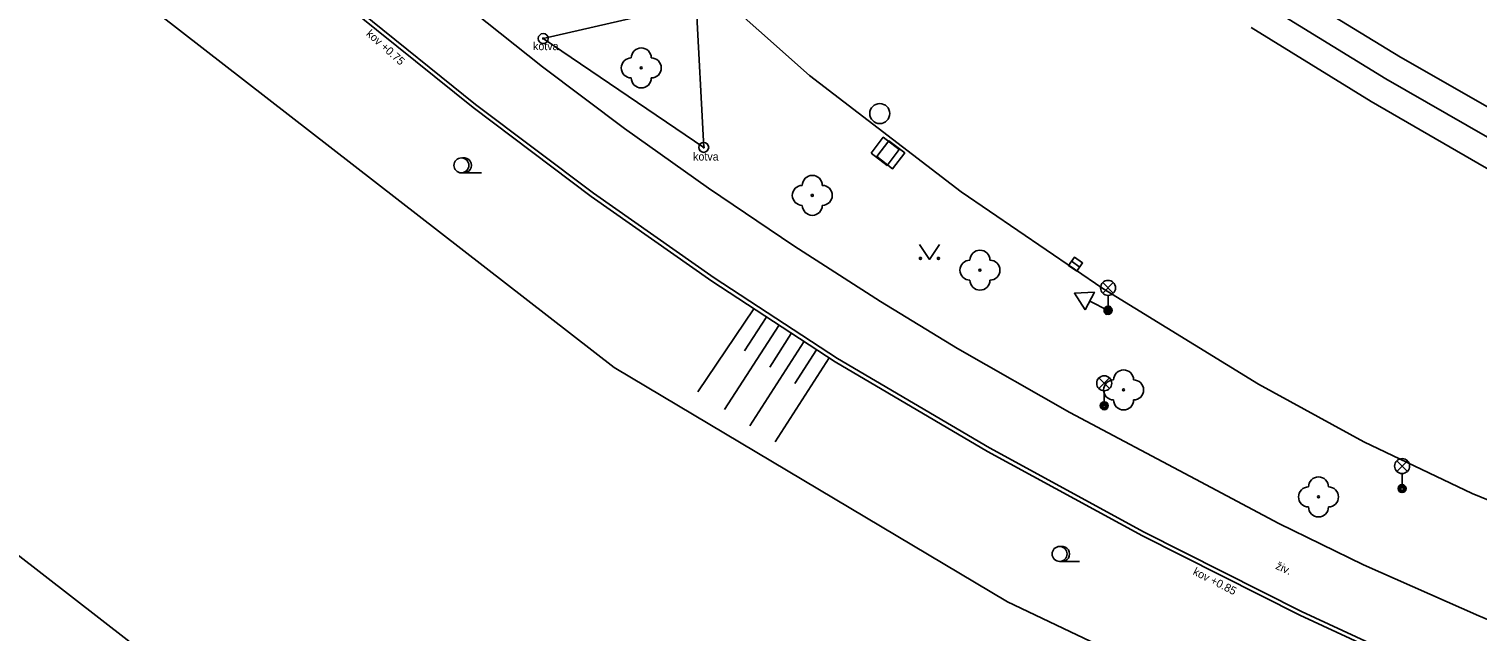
# Model space of a CAD drawing. Extents: x -598932 to -598196, y -1162207 to -1161504.
# Drawn here: x -598659.5 to -598587.2, y -1161999.2 to -1161969.1 of the extents above; entities that cross this region are included whole.
import ezdxf

# ---------------------------------------------------------------- set-up
doc = ezdxf.new("R2010")
doc.units = 0
for name, color, linetype in [('Level 22', 7, 'Continuous'), ('Level 25', 7, 'Continuous'), ('Level 26', 7, 'Continuous'), ('Level 27', 7, 'Continuous'), ('Level 33', 7, 'Continuous'), ('Level 34', 7, 'Continuous'), ('Level 36', 7, 'Continuous'), ('TM - CD - osa koleji', 7, 'Continuous'), ('TM - chodniky - VP', 7, 'Continuous'), ('TM - hladina vodniho toku_ bazenu_ nadrze', 7, 'Continuous'), ('TM - komunikace - VP', 7, 'Continuous'), ('TM - pomocna konstrukcna linie', 7, 'Continuous'), ('TM - popis povrchu', 7, 'Continuous'), ('TM - poznamka', 7, 'Continuous'), ('TM - rozhrani ploch obecne - VN', 7, 'Continuous'), ('TM - rozhrani ploch obecne - VP', 7, 'Continuous'), ('TM - srafovani', 7, 'Continuous'), ('TM - zabradli - VP', 7, 'Continuous')]:
    doc.layers.add(name, color=color, linetype=linetype)

msp = doc.modelspace()

# ---------------------------------------------------------------- linework, layer by layer
at = {"layer": 'Level 22'}
for centre in [(-598628.94, -1161971.06), (-598620.39, -1161977.43), (-598612.01, -1161981.17), (-598604.83, -1161987.16), (-598595.09, -1161992.51)]:
    msp.add_circle(centre, 0.05, dxfattribs=at)
for centre, start, end in [((-598628.94, -1161970.56), 0, 180), ((-598629.44, -1161971.06), 90, 270), ((-598628.44, -1161971.06), 270, 90), ((-598628.94, -1161971.56), 180, 0), ((-598620.89, -1161977.43), 90, 270), ((-598620.39, -1161976.93), 0, 180), ((-598619.89, -1161977.43), 270, 90), ((-598620.39, -1161977.93), 180, 0), ((-598612.01, -1161980.67), 0, 180), ((-598612.51, -1161981.17), 90, 270), ((-598611.51, -1161981.17), 270, 90), ((-598612.01, -1161981.67), 180, 0), ((-598604.83, -1161986.66), 0, 180), ((-598605.33, -1161987.16), 90, 270), ((-598604.33, -1161987.16), 270, 90), ((-598604.83, -1161987.66), 180, 0), ((-598595.59, -1161992.51), 90, 270), ((-598595.09, -1161992.01), 0, 180), ((-598594.59, -1161992.51), 270, 90), ((-598595.09, -1161993.01), 180, 0)]:
    msp.add_arc(centre, 0.5, start, end, dxfattribs=at)
at = {"layer": 'Level 25'}
for centre, radius in [((-598633.84, -1161969.59), 0.25), ((-598633.84, -1161969.59), 0.0303), ((-598625.82, -1161975.03), 0.25), ((-598625.82, -1161975.03), 0.0303)]:
    msp.add_circle(centre, radius, dxfattribs=at)
at = {"layer": 'Level 26'}
for points in [[(-598617.451, -1161975.323), (-598616.657, -1161975.931), (-598616.049, -1161975.137), (-598616.843, -1161974.529)], [(-598617.171, -1161975.493), (-598616.377, -1161976.101), (-598615.769, -1161975.307), (-598616.563, -1161974.699)]]:
    msp.add_lwpolyline(points, close=True, dxfattribs=at)
at = {"layer": 'Level 27'}
msp.add_line((-598607.435, -1161980.726), (-598607.025, -1161981.014), dxfattribs=at)
msp.add_lwpolyline([(-598607.578, -1161980.931), (-598607.169, -1161981.218), (-598606.882, -1161980.809), (-598607.291, -1161980.522)], close=True, dxfattribs=at)
msp.add_circle((-598617.02, -1161973.34), 0.5, dxfattribs=at)
at = {"layer": 'Level 33'}
for p, q in [((-598605.875, -1161982.32), (-598605.345, -1161981.79)), ((-598605.875, -1161981.79), (-598605.345, -1161982.32)), ((-598605.61, -1161982.43), (-598605.61, -1161983.18)), ((-598606.065, -1161987.09), (-598605.535, -1161986.56)), ((-598606.065, -1161986.56), (-598605.535, -1161987.09)), ((-598605.8, -1161987.2), (-598605.8, -1161987.95)), ((-598591.175, -1161991.23), (-598590.645, -1161990.7)), ((-598591.175, -1161990.7), (-598590.645, -1161991.23)), ((-598590.91, -1161991.34), (-598590.91, -1161992.09))]:
    msp.add_line(p, q, dxfattribs=at)
for centre, radius in [((-598605.61, -1161982.055), 0.375), ((-598605.61, -1161983.18), 0.2), ((-598605.61, -1161983.18), 0.145), ((-598605.61, -1161983.18), 0.0876), ((-598605.8, -1161986.825), 0.375), ((-598605.8, -1161987.95), 0.2), ((-598605.8, -1161987.95), 0.145), ((-598605.8, -1161987.95), 0.0876), ((-598590.91, -1161990.965), 0.375), ((-598590.91, -1161992.09), 0.2), ((-598590.91, -1161992.09), 0.145), ((-598590.91, -1161992.09), 0.0876)]:
    msp.add_circle(centre, radius, dxfattribs=at)
at = {"layer": 'Level 34'}
for p, q in [((-598606.516, -1161982.716), (-598605.61, -1161983.18)), ((-598605.724, -1161983.403), (-598605.496, -1161982.957))]:
    msp.add_line(p, q, dxfattribs=at)
msp.add_lwpolyline([(-598606.744, -1161983.161), (-598606.288, -1161982.271), (-598607.287, -1161982.321)], close=True, dxfattribs=at)
at = {"layer": 'Level 36'}
for p, q in [((-598637.93, -1161976.305), (-598636.93, -1161976.305)), ((-598608.03, -1161995.735), (-598607.03, -1161995.735))]:
    msp.add_line(p, q, dxfattribs=at)
msp.add_lwpolyline([(-598615.04, -1161979.88), (-598614.54, -1161980.63), (-598614.04, -1161979.88)], dxfattribs=at)
for centre, radius in [((-598637.93, -1161975.93), 0.375), ((-598614.99, -1161980.58), 0.05), ((-598614.091, -1161980.58), 0.05), ((-598608.03, -1161995.36), 0.375)]:
    msp.add_circle(centre, radius, dxfattribs=at)
for centre in [(-598637.805, -1161975.93), (-598607.905, -1161995.36)]:
    msp.add_arc(centre, 0.375, 260.40593, 99.59407, dxfattribs=at)
at = {"layer": 'TM - CD - osa koleji'}
msp.add_lwpolyline([(-598579.41, -1161978.43), (-598585.63, -1161975.11), (-598591.73, -1161971.61), (-598597.73, -1161967.92)], dxfattribs=at)
at = {"layer": 'TM - chodniky - VP'}
for points in [[(-598584.57, -1161999.51), (-598587.08, -1161998.45), (-598592.84, -1161995.91), (-598597.08, -1161993.84), (-598601.24, -1161991.62), (-598607.52, -1161988.29), (-598613.13, -1161985.08), (-598616.99, -1161982.73), (-598621.32, -1161979.95), (-598625.58, -1161977.07), (-598629.77, -1161974.09), (-598633.88, -1161971), (-598640.88, -1161965.42), (-598652.64, -1161955.19)], [(-598637.23, -1161972.88), (-598642.97, -1161968.26)], [(-598619.13, -1161985.59), (-598625.3, -1161981.55), (-598631.33, -1161977.32), (-598637.23, -1161972.88)], [(-598611.54, -1161990.06), (-598619.13, -1161985.59)], [(-598587.95, -1162001.94), (-598595.94, -1161998.24), (-598603.81, -1161994.27), (-598611.54, -1161990.06)]]:
    msp.add_lwpolyline(points, dxfattribs=at)
at = {"layer": 'TM - hladina vodniho toku_ bazenu_ nadrze'}
for points in [[(-598600.59, -1162002.54), (-598610.64, -1161997.76), (-598630.3, -1161986.03), (-598655.22, -1161966.67), (-598668.85, -1161955.4), (-598703.18, -1161923.15)], [(-598613.24, -1162025.43), (-598618.24, -1162022.67), (-598632.33, -1162014.28), (-598643.84, -1162006.97), (-598654.48, -1161999.77), (-598668.82, -1161988.66), (-598680.42, -1161979.19), (-598691.8, -1161968.94), (-598710.7, -1161950.21), (-598717.792, -1161943.174), (-598718.3, -1161942.67)]]:
    msp.add_lwpolyline(points, dxfattribs=at)
at = {"layer": 'TM - komunikace - VP'}
for points in [[(-598598.08, -1161986.87), (-598605.87, -1161982.08), (-598612.95, -1161977.26), (-598620.53, -1161971.43), (-598625.6, -1161966.92)], [(-598598.08, -1161986.87), (-598592.82, -1161989.75), (-598587.41, -1161992.34), (-598583.69, -1161993.86)]]:
    msp.add_lwpolyline(points, dxfattribs=at)
at = {"layer": 'TM - pomocna konstrukcna linie'}
msp.add_lwpolyline([(-598633.84, -1161969.59), (-598625.82, -1161975.03)], dxfattribs=at)
at = {"layer": 'TM - rozhrani ploch obecne - VN'}
for points in [[(-598633.84, -1161969.59), (-598626.2, -1161967.83)], [(-598626.2, -1161967.83), (-598625.82, -1161975.03)]]:
    msp.add_lwpolyline(points, dxfattribs=at)
at = {"layer": 'TM - rozhrani ploch obecne - VP'}
for points in [[(-598578.7, -1161977.28), (-598584.9, -1161974), (-598590.99, -1161970.52), (-598596.98, -1161966.86), (-598602.85, -1161963.02)], [(-598586.38, -1161976.25), (-598592.46, -1161972.73), (-598598.45, -1161969.03)]]:
    msp.add_lwpolyline(points, dxfattribs=at)
at = {"layer": 'TM - srafovani'}
for points in [[(-598623.32, -1161983.11), (-598626.11, -1161987.26)], [(-598622.07, -1161983.94), (-598624.78, -1161988.14)], [(-598622.7, -1161983.53), (-598623.78, -1161985.21)], [(-598620.81, -1161984.75), (-598623.52, -1161988.95)], [(-598621.44, -1161984.34), (-598622.52, -1161986.02)], [(-598619.55, -1161985.56), (-598622.25, -1161989.76)], [(-598620.18, -1161985.15), (-598621.26, -1161986.84)]]:
    msp.add_lwpolyline(points, dxfattribs=at)
at = {"layer": 'TM - zabradli - VP'}
for points in [[(-598637.35, -1161973.04), (-598643.1, -1161968.41)], [(-598619.24, -1161985.76), (-598625.41, -1161981.72), (-598631.45, -1161977.48), (-598637.35, -1161973.04)], [(-598619.24, -1161985.76), (-598611.63, -1161990.23), (-598603.89, -1161994.45), (-598596.02, -1161998.42), (-598588.01, -1162002.13)]]:
    msp.add_lwpolyline(points, dxfattribs=at)

# ---------------------------------------------------------------- texts
at = {"layer": 'TM - popis povrchu'}
msp.add_text('živ.', height=0.4, rotation=335.54455, dxfattribs=at).set_placement((-598597.27, -1161996.09))
at = {"layer": 'TM - poznamka'}
for s, rotation, p in [('kov +0.75', 318.16263, (-598642.72, -1161969.4)), ('kov +0.85', 333, (-598601.4, -1161996.37))]:
    msp.add_text(s, height=0.4, rotation=rotation, dxfattribs=at).set_placement(p)
for p in [(-598634.35, -1161970.17), (-598626.35, -1161975.69)]:
    msp.add_text('kotva', height=0.4, dxfattribs=at).set_placement(p)

doc.saveas('drawing.dxf')
